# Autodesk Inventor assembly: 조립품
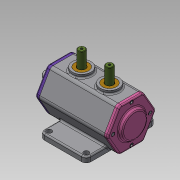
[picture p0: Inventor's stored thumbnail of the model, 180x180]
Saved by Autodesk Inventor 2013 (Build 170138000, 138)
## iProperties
Created: 2021-06
Part Number: 조립품
Document SubType Name: Assembly
Designer: hana-cad36
Author: hana-cad36
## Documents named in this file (11)
- C:\Documents and Settings\hana-cad36\바탕 화면\710606V1027\조립품.iam
- C:\Documents and Settings\hana-cad36\바탕 화면\710606V1027\본체.ipt
- C:\Documents and Settings\hana-cad36\바탕 화면\710606V1027\편심축.ipt
- C:\Documents and Settings\hana-cad36\바탕 화면\710606V1027\앞커버.ipt
- C:\Documents and Settings\hana-cad36\바탕 화면\710606V1027\베어링 6302.ipt
- C:\Documents and Settings\hana-cad36\바탕 화면\710606V1027\슬라이더.ipt
- C:\Documents and Settings\hana-cad36\바탕 화면\710606V1027\부시.ipt
- C:\Documents and Settings\hana-cad36\바탕 화면\710606V1027\뒷커버.ipt
- C:\Documents and Settings\hana-cad36\바탕 화면\710606V1027\베어링 6203.ipt
- C:\Documents and Settings\hana-cad36\바탕 화면\710606V1027\오일실.ipt
- C:\Documents and Settings\hana-cad36\바탕 화면\710606V1027\볼트 M4.ipt
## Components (10 placed, 3 different names)
1. 7-베어링 6203:1
2. 8-오일실:1
3. 9-M4-소켓머리:1
4. 9-M4-소켓머리:2
5. 9-M4-소켓머리:3
6. 9-M4-소켓머리:4
7. 9-M4-소켓머리:5
8. 9-M4-소켓머리:6
9. 9-M4-소켓머리:7
10. 9-M4-소켓머리:8
